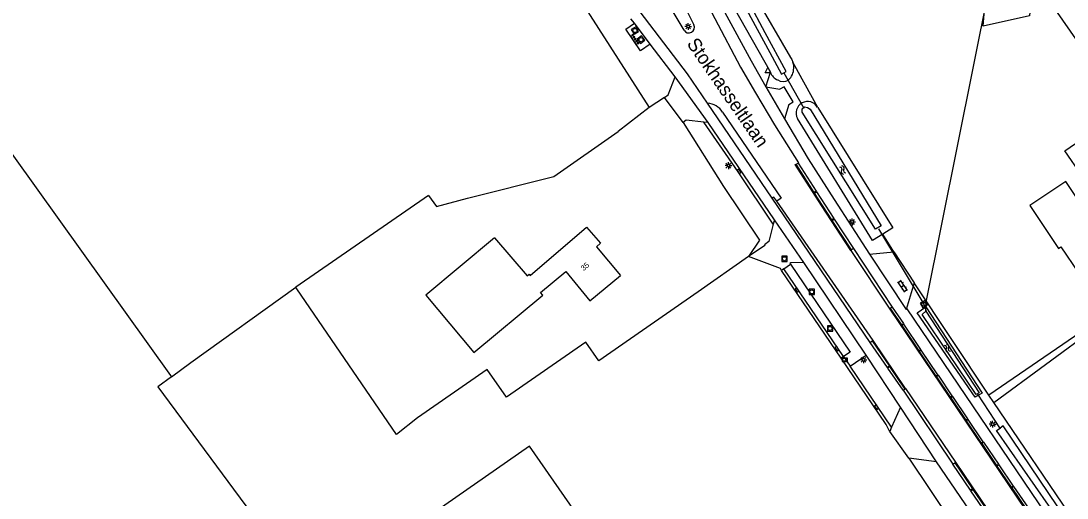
# Model space of a CAD drawing. Extents: x 133000 to 136000, y 400500 to 403500.
# Drawn here: x 133531.3 to 133725.1, y 400796.8 to 400885.1 of the extents above; entities that cross this region are included whole.
import ezdxf

# ---------------------------------------------------------------- set-up
doc = ezdxf.new("R2010")
doc.units = 0
for name, color, linetype in [('gg-afsc-draadraster', 7, 'Continuous'), ('gg-afsc-erfafscheiding', 7, 'Continuous'), ('gg-afsc-hekwerk', 7, 'Continuous'), ('gg-afsc-lijn draadraster', 7, 'Continuous'), ('gg-anno-huisnummerreeks BGT', 7, 'Continuous'), ('gg-anno-openbare ruimte label', 7, 'Continuous'), ('gg-bbg-bijgebouw', 7, 'Continuous'), ('gg-bbg-gedigitaliseerde bebouwing', 7, 'Continuous'), ('gg-bbg-gedigitaliseerde bijgebouw', 7, 'Continuous'), ('gg-bbg-hoofdgebouw', 7, 'Continuous'), ('gg-knt-bronhoudergrens', 7, 'Continuous'), ('gg-knt-verharding', 7, 'Continuous'), ('gg-knt-verharding nz', 7, 'Continuous'), ('gg-kntw-bovenkant insteek waterloop', 7, 'Continuous'), ('gg-kntw-waterlijn', 7, 'Continuous'), ('gg-kwrk-duiker nz buis', 7, 'Continuous'), ('gt-grn-groengrens', 7, 'Continuous'), ('gt-symb-informatiebord', 7, 'Continuous'), ('gt-symb-klinker verharding', 7, 'Continuous'), ('gt-symb-kolk', 7, 'Continuous'), ('gt-symb-lichtmast', 7, 'Continuous'), ('gt-symb-rioolschacht', 7, 'Continuous'), ('gt-symb-tegel verharding', 7, 'Continuous'), ('gt-symb-waterafsluiter', 7, 'Continuous'), ('gt-symb-watersymbool', 7, 'Continuous')]:
    doc.layers.add(name, color=color, linetype=linetype)

# ---------------------------------------------------------------- blocks, each defined once
blk = doc.blocks.new('gt0-RS')
at = {"layer": 'gt-symb-rioolschacht'}
blk.add_lwpolyline([(-0.5, -0.5), (0.5, -0.5), (0.5, 0.5), (-0.5, 0.5)], close=True, dxfattribs=at)
blk.add_circle((0, 0), 0.375, dxfattribs=at)
blk = doc.blocks.new('gt0-TEG1')
at = {"layer": 'gt-symb-tegel verharding'}
for p, q in [((-1.12, 0), (1.13, 0)), ((-0.9, -0.25), (-0.9, 0.25)), ((-0.45, -0.25), (-0.45, 0.25)), ((0, -0.25), (0, 0.25)), ((0.45, -0.25), (0.45, 0.25)), ((0.9, -0.25), (0.9, 0.25))]:
    blk.add_line(p, q, dxfattribs=at)
blk = doc.blocks.new('gt0-LMAST')
at = {"layer": 'gt-symb-lichtmast'}
for p, q in [((-0.18, 0.17), (-0.45, 0.44)), ((-0.01, 0.25), (-0.01, 0.62)), ((0.17, 0.17), (0.44, 0.44)), ((-0.26, 0), (-0.63, 0)), ((-0.18, -0.18), (-0.45, -0.45)), ((-0.01, -0.25), (-0.01, -0.63)), ((0.44, -0.45), (0.17, -0.18)), ((0.24, 0), (0.62, 0))]:
    blk.add_line(p, q, dxfattribs=at)
blk.add_circle((-0.01, 0), 0.25, dxfattribs=at)
blk = doc.blocks.new('gt0-WAFSL')
at = {"layer": 'gt-symb-waterafsluiter'}
for p, q in [((-0.5, -0.33), (0, 0.67)), ((0, 0.67), (0.5, -0.33)), ((0.5, -0.33), (-0.5, -0.33))]:
    blk.add_line(p, q, dxfattribs=at)
blk = doc.blocks.new('gt0-WA')
at = {"layer": 'gt-symb-watersymbool'}
for centre, start, end in [((-0.32, 0.02), 28.0725, 151.9275), ((0.43, 0.42), 208.0725, 331.9275), ((-0.32, -0.43), 28.0725, 151.9275), ((0.43, -0.03), 208.0725, 331.9275)]:
    blk.add_arc(centre, 0.425, start, end, dxfattribs=at)
blk = doc.blocks.new('gt0-KL1')
at = {"layer": 'gt-symb-klinker verharding'}
for p, q in [((-1.15, 0.3), (1.15, 0.3)), ((-1, -0.3), (-1, 0.3)), ((-0.5, 0.3), (-0.5, 0.45)), ((0, -0.3), (0, 0.3)), ((0.5, 0.3), (0.5, 0.45)), ((1, -0.3), (1, 0.3)), ((-1.15, -0.3), (1.15, -0.3)), ((-0.5, -0.45), (-0.5, -0.3)), ((0.5, -0.45), (0.5, -0.3))]:
    blk.add_line(p, q, dxfattribs=at)
blk = doc.blocks.new('gt0-KOLK')
at = {"layer": 'gt-symb-kolk'}
blk.add_lwpolyline([(0, 0), (0.38, 0), (0.38, 0.4), (-0.37, 0.4), (-0.37, 0), (0, 0)], dxfattribs=at)
blk = doc.blocks.new('gt0-IBORD')
at = {"layer": 'gt-symb-informatiebord'}
blk.add_lwpolyline([(-0.5, 0.29), (-0.5, -0.29), (0.5, -0.29), (0.5, 0.29), (-0.5, 0.29)], dxfattribs=at)
blk.add_lwpolyline([(-0.42, -0.21), (0.42, -0.21), (0.42, 0.21), (-0.42, 0.21)], close=True, dxfattribs=at)

msp = doc.modelspace()

# ---------------------------------------------------------------- linework, layer by layer
at = {"layer": 'gg-afsc-draadraster'}
for p, q in [((133606.83, 400852.74), (133582.21, 400835.79)), ((133559.02, 400819.43), (133559.19, 400819.2))]:
    msp.add_line(p, q, dxfattribs=at)
for points in [[(133447.98, 400921.16), (133465.18, 400915.92), (133478.54, 400914.86), (133484.89, 400916.85), (133521.8, 400871.34), (133559.02, 400819.43)], [(133606.83, 400852.74), (133608.26, 400850.71), (133614, 400852.28), (133630.01, 400856.26), (133641.93, 400864.59)]]:
    msp.add_lwpolyline(points, dxfattribs=at)
at = {"layer": 'gg-afsc-erfafscheiding'}
for p, q in [((133632.15, 400893.31), (133647.65, 400869.06)), ((133647.65, 400869.06), (133641.93, 400864.59))]:
    msp.add_line(p, q, dxfattribs=at)
at = {"layer": 'gg-afsc-hekwerk'}
for p, q in [((133666.08, 400841.48), (133656.77, 400834.94)), ((133683.23, 400822.66), (133672.21, 400838.89)), ((133695.81, 400804.17), (133692.24, 400809.07)), ((133695.81, 400804.17), (133722.36, 400764.39))]:
    msp.add_line(p, q, dxfattribs=at)
for points in [[(133661.43, 400854.4), (133668.12, 400844.49), (133666.08, 400841.48)], [(133672.21, 400838.89), (133671.98, 400839.23), (133666.08, 400841.48)], [(133559.19, 400819.2), (133562.79, 400821.86), (133582.21, 400835.79)], [(133656.77, 400834.94), (133638.36, 400822.15), (133635.94, 400825.63), (133621.24, 400815.41), (133617.67, 400820.55), (133604.79, 400811.59), (133600.85, 400808.53), (133582.43, 400835.48), (133582.21, 400835.79)], [(133692.24, 400809.07), (133692.17, 400809.17), (133691.58, 400810.35), (133683.23, 400822.66)], [(133559.19, 400819.2), (133556.66, 400817.33), (133580.47, 400785.12), (133579.84, 400783.88), (133577.32, 400779.54), (133542.47, 400754.82)]]:
    msp.add_lwpolyline(points, dxfattribs=at)
at = {"layer": 'gg-afsc-lijn draadraster'}
msp.add_lwpolyline([(133758.59, 400866.92), (133780.49, 400833.35), (133763.78, 400822.45), (133750.39, 400842.98), (133710.62, 400815.8)], dxfattribs=at)
at = {"layer": 'gg-bbg-bijgebouw'}
msp.add_lwpolyline([(133721.43, 400889.35), (133727.08, 400881.11), (133739.85, 400889.81)], dxfattribs=at)
at = {"layer": 'gg-bbg-gedigitaliseerde bebouwing'}
msp.add_lwpolyline([(133619.03, 400844.92), (133606.33, 400834.3), (133615.2, 400823.7), (133627.98, 400834.29), (133627.56, 400834.8), (133632.23, 400838.68), (133636.7, 400833.28), (133642.36, 400837.94)], dxfattribs=at)
at = {"layer": 'gg-bbg-gedigitaliseerde bijgebouw'}
msp.add_lwpolyline([(133734.15, 400867.47), (133737.27, 400862.92), (133727.82, 400856.45), (133724.7, 400861.01), (133734.15, 400867.47)], dxfattribs=at)
at = {"layer": 'gg-bbg-hoofdgebouw'}
for points in [[(133727, 400837.77), (133728.72, 400838.92), (133729.02, 400838.46), (133729.63, 400838.87), (133730.99, 400836.83), (133732.49, 400836.51), (133734.83, 400838.07), (133735.1, 400839.59), (133733.45, 400842.07), (133733.65, 400842.21), (133724.87, 400855.37), (133718.2, 400850.91)], [(133718.2, 400850.91), (133723.52, 400842.97), (133723.96, 400843.26), (133727.21, 400838.42), (133726.76, 400838.13), (133727, 400837.77)], [(133619.03, 400844.92), (133625.06, 400837.88), (133625.42, 400838.19), (133625.65, 400837.92), (133636.05, 400846.91), (133638.69, 400843.95), (133637.94, 400843.28), (133642.36, 400837.94)], [(133643.51, 400789.11), (133639.46, 400786.3), (133625.53, 400806.35), (133562.16, 400762.27), (133564.97, 400758.11), (133557.08, 400752.79), (133579.25, 400720.86), (133594.91, 400731.8), (133616.92, 400700.29), (133662.25, 400731.85), (133667.72, 400723.93), (133677.93, 400731.05), (133677.59, 400731.53)]]:
    msp.add_lwpolyline(points, dxfattribs=at)
at = {"layer": 'gg-knt-bronhoudergrens'}
for p, q in [((133711.52, 400814.47), (133710.62, 400815.8)), ((133745.11, 400764.98), (133711.52, 400814.47))]:
    msp.add_line(p, q, dxfattribs=at)
msp.add_lwpolyline([(133711.52, 400814.47), (133740.25, 400835.56), (133750.39, 400842.98), (133763.78, 400822.45), (133780.49, 400833.35), (133758.59, 400866.92)], dxfattribs=at)
at = {"layer": 'gg-knt-verharding'}
for p, q in [((133651.5, 400887.69), (133654.13, 400883.33)), ((133653.64, 400888.98), (133655.96, 400884.32)), ((133644.97, 400884.64), (133644.28, 400885.44)), ((133647.89, 400880.76), (133644.97, 400884.64)), ((133652.49, 400874.74), (133647.89, 400880.76)), ((133658.59, 400866.25), (133652.49, 400874.74)), ((133669.28, 400872.89), (133671.91, 400872.41)), ((133669.28, 400872.89), (133672.77, 400866.93)), ((133653.96, 400866.24), (133650.51, 400870.88)), ((133673.56, 400869.6), (133672.77, 400866.93)), ((133670.9, 400848.28), (133658.59, 400866.25)), ((133674.9, 400858.55), (133675.26, 400858.74)), ((133675.26, 400858.74), (133678.61, 400853.54)), ((133678.69, 400853.41), (133681.89, 400848.48)), ((133676.3, 400840.33), (133670.9, 400848.28)), ((133681.97, 400848.37), (133685.52, 400842.94)), ((133685.52, 400842.94), (133685.14, 400842.68)), ((133688.49, 400841.92), (133693, 400842.35)), ((133688.49, 400841.92), (133695.26, 400831.67)), ((133693, 400842.35), (133696.78, 400836.61)), ((133672.65, 400839.2), (133673.87, 400840.02)), ((133683.68, 400822.97), (133672.65, 400839.2)), ((133687.9, 400823.22), (133676.3, 400840.33)), ((133696.78, 400836.61), (133695.26, 400831.67)), ((133692.72, 400832.09), (133692.35, 400831.82)), ((133692.72, 400832.09), (133694.77, 400829.05)), ((133698.01, 400824.27), (133694.85, 400828.94)), ((133688.62, 400825.58), (133689.01, 400825.85)), ((133691.8, 400820.94), (133688.62, 400825.58)), ((133684.89, 400821.19), (133687.9, 400823.22)), ((133694.23, 400813.58), (133687.9, 400823.22)), ((133701.18, 400819.59), (133698.09, 400824.16)), ((133692.59, 400809.86), (133684.89, 400821.19)), ((133694.71, 400816.7), (133691.87, 400820.83)), ((133703.83, 400815.67), (133701.26, 400819.48)), ((133694.71, 400816.7), (133695.08, 400816.94)), ((133706.72, 400811.4), (133703.92, 400815.54)), ((133694.23, 400813.58), (133692.59, 400809.86)), ((133700.88, 400803.49), (133694.23, 400813.58)), ((133709.57, 400807.19), (133706.79, 400811.3)), ((133709.57, 400807.19), (133709.64, 400807.08)), ((133709.64, 400807.08), (133712.39, 400803.03)), ((133700.88, 400803.49), (133695.81, 400804.17)), ((133703.96, 400803.03), (133704.32, 400803.29)), ((133707.21, 400798.22), (133703.96, 400803.03)), ((133712.39, 400803.03), (133712.47, 400802.91)), ((133712.47, 400802.91), (133715.12, 400798.99)), ((133710.23, 400793.78), (133707.29, 400798.1)), ((133715.12, 400798.99), (133715.2, 400798.88)), ((133715.2, 400798.88), (133717.92, 400794.87))]:
    msp.add_line(p, q, dxfattribs=at)
for points in [[(133658.12, 400893.46), (133661.67, 400886.59), (133666.58, 400877.67), (133669.28, 400872.89)], [(133647.89, 400880.76), (133646.1, 400879.52), (133643.36, 400883.51), (133644.97, 400884.64)], [(133650.51, 400870.88), (133651.19, 400871.38), (133652.49, 400874.74)], [(133673.56, 400869.6), (133674.37, 400870.06), (133672.69, 400872.89), (133671.91, 400872.41)], [(133657.79, 400866.31), (133654.54, 400866.69), (133653.96, 400866.24)], [(133670.64, 400847.46), (133664.15, 400857.11), (133657.79, 400866.31)], [(133672.77, 400866.93), (133677.14, 400859.54), (133681.94, 400852.04), (133688.49, 400841.92)], [(133678.61, 400853.54), (133678.23, 400853.29), (133674.9, 400858.55)], [(133681.89, 400848.48), (133681.52, 400848.24), (133678.31, 400853.17), (133678.69, 400853.41)], [(133670.64, 400847.46), (133669.82, 400844.21), (133669.04, 400843.64), (133669.12, 400843.48), (133666.08, 400841.48)], [(133685.14, 400842.68), (133681.59, 400848.12), (133681.97, 400848.37)], [(133673.87, 400840.02), (133684.94, 400823.79), (133683.68, 400822.97)], [(133692.35, 400831.82), (133694.4, 400828.8), (133694.77, 400829.05)], [(133695.26, 400831.67), (133695.43, 400831.78), (133726.57, 400785.77), (133740.83, 400764.74)], [(133694.85, 400828.94), (133694.47, 400828.68), (133697.63, 400824.02), (133698.01, 400824.27)], [(133689.01, 400825.85), (133692.18, 400821.2), (133691.8, 400820.94)], [(133698.09, 400824.16), (133697.71, 400823.91), (133700.81, 400819.33), (133701.18, 400819.59)], [(133695.08, 400816.94), (133692.25, 400821.09), (133691.87, 400820.83)], [(133701.26, 400819.48), (133700.88, 400819.22), (133703.46, 400815.42), (133703.83, 400815.67)], [(133703.92, 400815.54), (133703.55, 400815.29), (133706.35, 400811.15), (133706.72, 400811.4)], [(133706.79, 400811.3), (133706.42, 400811.05), (133709.2, 400806.95), (133709.57, 400807.19)], [(133709.64, 400807.08), (133709.28, 400806.84), (133712.02, 400802.79), (133712.39, 400803.03)], [(133724.97, 400768.47), (133723.32, 400770.82), (133722.13, 400772.37), (133700.88, 400803.49)], [(133704.32, 400803.29), (133707.58, 400798.47), (133707.21, 400798.22)], [(133712.47, 400802.91), (133712.1, 400802.66), (133714.76, 400798.75), (133715.12, 400798.99)], [(133707.29, 400798.1), (133707.66, 400798.35), (133710.59, 400794.02), (133710.23, 400793.78)], [(133715.2, 400798.88), (133714.83, 400798.64), (133717.55, 400794.62), (133717.92, 400794.87)]]:
    msp.add_lwpolyline(points, dxfattribs=at)
msp.add_arc((133655.01, 400883.89), 1.04, 212.4001, 24.4213, dxfattribs=at)
at = {"layer": 'gg-knt-verharding nz'}
for p, q in [((133670.49, 400852.23), (133658.5, 400869.84)), ((133658.59, 400866.25), (133657.79, 400866.31)), ((133678.69, 400853.41), (133678.61, 400853.54)), ((133688.62, 400825.58), (133670.49, 400852.23)), ((133689.15, 400825.94), (133671.3, 400851.68)), ((133681.97, 400848.37), (133681.89, 400848.48)), ((133670.9, 400848.28), (133670.64, 400847.46)), ((133685.01, 400842.6), (133685.14, 400842.68)), ((133685.01, 400842.6), (133692.23, 400831.73)), ((133685.52, 400842.94), (133692.72, 400832.09)), ((133672.65, 400839.2), (133672.21, 400838.89)), ((133692.23, 400831.73), (133692.35, 400831.82)), ((133692.23, 400831.73), (133737.23, 400765.28)), ((133694.77, 400829.05), (133694.85, 400828.94)), ((133689.15, 400825.94), (133689.01, 400825.85)), ((133695.19, 400817.01), (133689.15, 400825.94)), ((133698.01, 400824.27), (133698.09, 400824.16)), ((133683.68, 400822.97), (133683.23, 400822.66)), ((133683.68, 400822.97), (133684.89, 400821.19)), ((133691.8, 400820.94), (133691.87, 400820.83)), ((133701.18, 400819.59), (133701.26, 400819.48)), ((133694.71, 400816.7), (133703.96, 400803.03)), ((133695.19, 400817.01), (133695.08, 400816.94)), ((133695.19, 400817.01), (133704.45, 400803.38)), ((133703.83, 400815.67), (133703.92, 400815.54)), ((133692.59, 400809.86), (133692.24, 400809.07)), ((133706.72, 400811.4), (133706.79, 400811.3)), ((133704.45, 400803.38), (133704.32, 400803.29)), ((133704.45, 400803.38), (133726.01, 400771.53)), ((133707.21, 400798.22), (133707.29, 400798.1))]:
    msp.add_line(p, q, dxfattribs=at)
for points in [[(133656.18, 400892.48), (133659.83, 400885.48), (133664.62, 400876.53), (133667.39, 400871.76), (133670.91, 400865.82), (133675.34, 400858.79), (133675.26, 400858.74)], [(133658.5, 400869.84), (133654.75, 400875.27), (133646, 400886.71)], [(133661.29, 400868.19), (133672.11, 400852.24), (133671.3, 400851.68)], [(133685.01, 400842.6), (133679.61, 400850.89), (133674.75, 400858.47), (133674.9, 400858.55)], [(133671.3, 400851.68), (133670.77, 400852.43), (133670.49, 400852.23)], [(133676.3, 400840.33), (133673.94, 400840.3), (133673.76, 400840.18), (133673.87, 400840.02)]]:
    msp.add_lwpolyline(points, dxfattribs=at)
msp.add_arc((133658.19, 400866.15), 3.71, 33.4459, 85.2156, dxfattribs=at)
at = {"layer": 'gg-kntw-bovenkant insteek waterloop'}
for p, q in [((133678.9, 400869.06), (133692.79, 400846.74)), ((133692.79, 400846.74), (133690.98, 400845.62)), ((133698.95, 400832.16), (133709.34, 400816.17)), ((133709.34, 400816.17), (133708.68, 400815.8))]:
    msp.add_line(p, q, dxfattribs=at)
for points in [[(133647.32, 400922.51), (133651.05, 400912.57), (133655.81, 400902.73), (133663.36, 400887.54), (133670.14, 400875.56)], [(133660.15, 400904.98), (133667.27, 400889.72), (133673.84, 400878.31), (133674.12, 400877.9), (133674.32, 400877.44)], [(133674.47, 400876.33), (133674.45, 400876.89), (133674.32, 400877.44)], [(133690.98, 400845.62), (133689.08, 400844.44), (133675.14, 400866.99)], [(133708.68, 400815.8), (133708.05, 400815.44), (133697.32, 400831.04), (133698.95, 400832.16)], [(133724.6, 400792.37), (133724.06, 400792.01), (133712.04, 400809.28), (133712.69, 400809.71)], [(133724.6, 400792.37), (133725.07, 400792.69), (133713.28, 400810.1), (133712.69, 400809.71)]]:
    msp.add_lwpolyline(points, dxfattribs=at)
for centre, radius, start, end in [((133672.47, 400876.41), 2.48, 200.0591, 246.5071), ((133671.54, 400876.32), 2.92, 311.3827, 0.1185), ((133672.49, 400875.87), 2.01, 240.0041, 299.594), ((133677.03, 400868), 2.14, 29.6335, 207.9588)]:
    msp.add_arc(centre, radius, start, end, dxfattribs=at)
at = {"layer": 'gg-kntw-waterlijn'}
for points in [[(133663.36, 400891.53), (133670.02, 400879.23), (133672.21, 400875.2), (133673.08, 400875.67), (133669.18, 400882.87), (133660.12, 400899.95)], [(133676.02, 400868.19), (133676.02, 400868.78), (133676.46, 400869.15), (133677.03, 400869.03), (133677.52, 400868.71), (133690.66, 400847.15), (133689.59, 400846.5), (133676.02, 400868.19)], [(133698.33, 400830.81), (133698.9, 400831.32), (133708.81, 400816.26), (133708.28, 400815.91), (133698.22, 400830.72), (133698.33, 400830.81)]]:
    msp.add_lwpolyline(points, dxfattribs=at)
at = {"layer": 'gg-kwrk-duiker nz buis'}
for p, q in [((133676.4, 400868.88), (133672.66, 400875.36)), ((133712.78, 400809.58), (133708.56, 400815.97))]:
    msp.add_line(p, q, dxfattribs=at)
for points in [[(133698.9, 400831.32), (133699, 400833), (133713.54, 400905.54)], [(133690.18, 400846.6), (133698.57, 400832.66), (133699.01, 400831.37)]]:
    msp.add_lwpolyline(points, dxfattribs=at)
at = {"layer": 'gt-grn-groengrens'}
for p, q in [((133669.28, 400872.89), (133670.14, 400875.56)), ((133675.35, 400875.54), (133674.32, 400877.44)), ((133678.9, 400869.06), (133675.35, 400875.54)), ((133650.51, 400870.88), (133647.65, 400869.06)), ((133653.96, 400866.24), (133661.43, 400854.4)), ((133693, 400842.35), (133690.98, 400845.62)), ((133710.62, 400815.8), (133696.78, 400836.61))]:
    msp.add_line(p, q, dxfattribs=at)
msp.add_lwpolyline([(133719.63, 400903.41), (133718.16, 400886), (133709.53, 400884.07), (133710.59, 400897.1), (133711.52, 400905.49)], dxfattribs=at)

# ---------------------------------------------------------------- block references
at = {"layer": 'gt-symb-informatiebord'}
msp.add_blockref('gt0-IBORD', (133683.93, 400822.35), dxfattribs=at)
at = {"layer": 'gt-symb-klinker verharding', "rotation": 123.5788137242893}
msp.add_blockref('gt0-KL1', (133694.65, 400835.98), dxfattribs=at)
at = {"layer": 'gt-symb-kolk'}
for p, rotation in [((133664.15, 400857.11), -56.07044606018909), ((133675.24, 400835.38), 124.18020305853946), ((133682.63, 400824.51), 124.18020305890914), ((133689.98, 400813.71), 124.2138335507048)]:
    msp.add_blockref('gt0-KOLK', p, dxfattribs=dict(at, rotation=rotation))
at = {"layer": 'gt-symb-lichtmast'}
for p in [(133654.9, 400884.04), (133662.36, 400858.28), (133685.29, 400847.86), (133687.38, 400822.34), (133711.32, 400810.44)]:
    msp.add_blockref('gt0-LMAST', p, dxfattribs=at)
at = {"layer": 'gt-symb-rioolschacht'}
for p, rotation in [((133645.04, 400883.28), 121.00306752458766), ((133646.17, 400881.59), -52.96961039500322), ((133698.56, 400832.65), -149.4095645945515)]:
    msp.add_blockref('gt0-RS', p, dxfattribs=dict(at, rotation=rotation))
for p in [(133672.74, 400841.05), (133677.8, 400834.91), (133681.19, 400828.15)]:
    msp.add_blockref('gt0-RS', p, dxfattribs=at)
at = {"layer": 'gt-symb-tegel verharding', "rotation": -55.547516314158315}
msp.add_blockref('gt0-TEG1', (133645.09, 400881.71), dxfattribs=at)
at = {"layer": 'gt-symb-waterafsluiter'}
msp.add_blockref('gt0-WAFSL', (133669.67, 400875.76), dxfattribs=at)
at = {"layer": 'gt-symb-watersymbool', "rotation": -60.511092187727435}
for p in [(133683.51, 400857.52), (133702.9, 400824.52)]:
    msp.add_blockref('gt0-WA', p, dxfattribs=at)

# ---------------------------------------------------------------- texts
at = {"layer": 'gg-anno-huisnummerreeks BGT'}
msp.add_text('35', height=1, rotation=39.6, dxfattribs=at).set_placement((133635.51, 400838.73))
at = {"layer": 'gg-anno-openbare ruimte label'}
msp.add_text('Stokhasseltlaan', height=2.5, rotation=304.6, dxfattribs=at).set_placement((133654.55, 400880.83))

doc.saveas('drawing.dxf')
